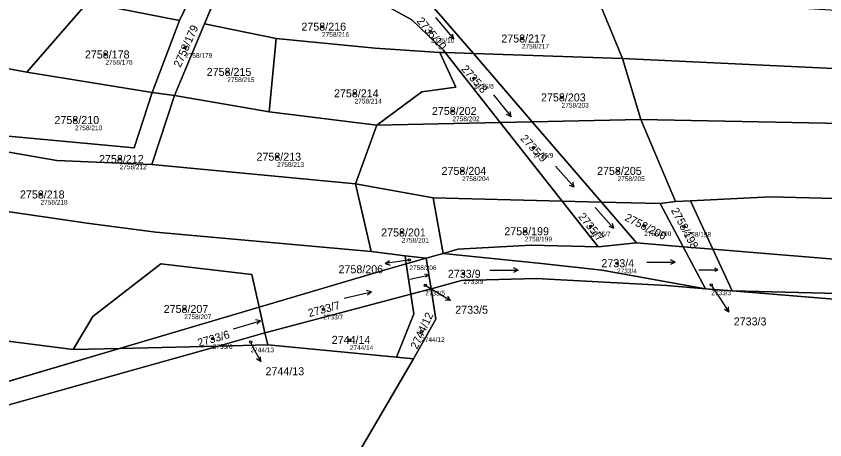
# Model space of a CAD drawing. Extents: x -739214 to -733252, y -1147612 to -1142842.
# Drawn here: x -737857.5 to -737685.7, y -1144474 to -1144384.1 of the extents above; entities that cross this region are included whole.
import ezdxf

# ---------------------------------------------------------------- set-up
doc = ezdxf.new("R2010")
doc.units = 0
for name, color, linetype in [('Definiční body', 7, 'Continuous'), ('Hranice parcel', 7, 'Continuous'), ('Parcelní čísla', 7, 'Continuous'), ('Polygon parcely', 7, 'Continuous'), ('Pop  PČ popisy', 7, 'Continuous'), ('Značky kultur', 7, 'Continuous')]:
    doc.layers.add(name, color=color, linetype=linetype)

msp = doc.modelspace()

# ---------------------------------------------------------------- linework, layer by layer
at = {"layer": 'Definiční body'}
for centre in [(-737792.56, -1144386.29), (-737769.43, -1144387.53), (-737750.1, -1144388.81), (-737821.63, -1144390.75), (-737838.55, -1144392.2), (-737812.68, -1144395.9), (-737760.29, -1144397.29), (-737785.64, -1144400.45), (-737741.66, -1144401.32), (-737764.84, -1144404.2), (-737845.01, -1144406.12), (-737747.64, -1144411.98), (-737835.55, -1144414.41), (-737802.1, -1144413.91), (-737762.79, -1144416.92), (-737729.76, -1144416.92), (-737852.35, -1144421.92), (-737735.48, -1144428.69), (-737724.13, -1144428.58), (-737715.67, -1144428.74), (-737775.62, -1144429.99), (-737749.46, -1144429.73), (-737773.99, -1144435.82), (-737729.9, -1144436.51), (-737762.51, -1144438.76), (-737770.64, -1144441.21), (-737709.88, -1144441.15), (-737821.82, -1144446.23), (-737792.3, -1144446.29), (-737771.49, -1144451.07), (-737815.77, -1144452.55), (-737786.65, -1144452.79), (-737807.74, -1144453.26)]:
    msp.add_circle(centre, 0.25, dxfattribs=at)
at = {"layer": 'Hranice parcel'}
for p, q in [((-737819.16, -1144377.29), (-737822.86, -1144384.96)), ((-737817.51, -1144385.68), (-737814.34, -1144378.15)), ((-737855.23, -1144395.98), (-737842.4, -1144381.17)), ((-737822.86, -1144384.96), (-737842.4, -1144381.17)), ((-737760.41, -1144392.01), (-737769.21, -1144381.81)), ((-737733.64, -1144381.24), (-737728.72, -1144393.06)), ((-737828.63, -1144400.28), (-737822.86, -1144384.96)), ((-737823.9, -1144400.88), (-737817.51, -1144385.68)), ((-737802.29, -1144388.83), (-737817.51, -1144385.68)), ((-737802.29, -1144388.83), (-737803.75, -1144404.41)), ((-737766.39, -1144391.81), (-737767.52, -1144391.77)), ((-737760.41, -1144392.01), (-737766.39, -1144391.81)), ((-737766.39, -1144391.81), (-737754.7, -1144406.64)), ((-737747.91, -1144406.5), (-737760.41, -1144392.01)), ((-737728.72, -1144393.06), (-737760.41, -1144392.01)), ((-737728.72, -1144393.06), (-737724.82, -1144406.02)), ((-737860.24, -1144395.01), (-737855.23, -1144395.98)), ((-737855.23, -1144395.98), (-737828.63, -1144400.28)), ((-737828.71, -1144415.54), (-737823.9, -1144400.88)), ((-737828.63, -1144400.28), (-737823.9, -1144400.88)), ((-737780.88, -1144407.18), (-737803.75, -1144404.41)), ((-737747.91, -1144406.5), (-737724.82, -1144406.02)), ((-737724.82, -1144406.02), (-737717.47, -1144423.41)), ((-737780.88, -1144407.18), (-737785.47, -1144419.68)), ((-737780.88, -1144407.18), (-737754.7, -1144406.64)), ((-737754.7, -1144406.64), (-737747.91, -1144406.5)), ((-737754.7, -1144406.64), (-737741.55, -1144423.32)), ((-737733.22, -1144423.53), (-737747.91, -1144406.5)), ((-737828.71, -1144415.54), (-737785.47, -1144419.68)), ((-737768.93, -1144422.63), (-737785.47, -1144419.68)), ((-737785.47, -1144419.68), (-737782.1, -1144434.06)), ((-737741.55, -1144423.32), (-737768.93, -1144422.63)), ((-737768.93, -1144422.63), (-737766.81, -1144434.44)), ((-737733.22, -1144423.53), (-737741.55, -1144423.32)), ((-737741.55, -1144423.32), (-737733.87, -1144433.07)), ((-737717.47, -1144423.41), (-737720.76, -1144423.85)), ((-737717.47, -1144423.41), (-737714.28, -1144423.29)), ((-737714.28, -1144423.29), (-737709.52, -1144433.54)), ((-737720.76, -1144423.85), (-737733.22, -1144423.53)), ((-737725.73, -1144432.21), (-737733.22, -1144423.53)), ((-737720.76, -1144423.85), (-737715.85, -1144433.02)), ((-737725.73, -1144432.21), (-737733.87, -1144433.07)), ((-737715.85, -1144433.02), (-737725.73, -1144432.21)), ((-737709.52, -1144433.54), (-737715.85, -1144433.02)), ((-737715.85, -1144433.02), (-737711.09, -1144441.92)), ((-737709.52, -1144433.54), (-737705.41, -1144442.38)), ((-737782.1, -1144434.06), (-737774.89, -1144434.96)), ((-737774.89, -1144434.96), (-737770.45, -1144435.47)), ((-737774.89, -1144434.96), (-737774.65, -1144436.65)), ((-737766.81, -1144434.44), (-737770.45, -1144435.47)), ((-737770.45, -1144435.47), (-737774.65, -1144436.65)), ((-737774.65, -1144436.65), (-737773.72, -1144443.09)), ((-737769.4, -1144441.94), (-737770.45, -1144435.47)), ((-737773.72, -1144443.09), (-737769.4, -1144441.94)), ((-737711.09, -1144441.92), (-737705.41, -1144442.38)), ((-737805.91, -1144445.83), (-737835.54, -1144454.6)), ((-737804.67, -1144451.31), (-737805.91, -1144445.83)), ((-737814.62, -1144454.1), (-737804.67, -1144451.31)), ((-737804.09, -1144453.85), (-737804.67, -1144451.31)), ((-737835.54, -1144454.6), (-737814.62, -1144454.1)), ((-737814.62, -1144454.1), (-737804.09, -1144453.85)), ((-737804.09, -1144453.85), (-737776.7, -1144456.47)), ((-737835.54, -1144454.6), (-737868.17, -1144464.26)), ((-737845.4, -1144454.84), (-737835.54, -1144454.6)), ((-737773.14, -1144456.81), (-737785.6, -1144478.09)), ((-737776.7, -1144456.47), (-737773.14, -1144456.81))]:
    msp.add_line(p, q, dxfattribs=at)
for points in [[(-737779.31, -1144381.64), (-737773.51, -1144384.84), (-737766.78, -1144391.31), (-737766.39, -1144391.81)], [(-737767.52, -1144391.77), (-737781.29, -1144390.88), (-737802.29, -1144388.83)], [(-737767.52, -1144391.77), (-737764.14, -1144399.15), (-737771.37, -1144400.16), (-737780.88, -1144407.18)], [(-737728.72, -1144393.06), (-737671.96, -1144395.77), (-737644.37, -1144397.73), (-737563.33, -1144405.98), (-737533.61, -1144409.53), (-737522.36, -1144411.87)], [(-737861.54, -1144409.35), (-737832.48, -1144412.05), (-737828.63, -1144400.28)], [(-737803.75, -1144404.41), (-737816.86, -1144402.11), (-737823.9, -1144400.88)], [(-737922.34, -1144401.98), (-737848.89, -1144414.72), (-737828.71, -1144415.54)], [(-737724.82, -1144406.02), (-737667.68, -1144407.14), (-737645.7, -1144408.73), (-737578.7, -1144416.54), (-737542.83, -1144418.76), (-737511.58, -1144424.84)], [(-737782.1, -1144434.06), (-737827.86, -1144429.94), (-737841.91, -1144428.1), (-737862.38, -1144425.14), (-737892.14, -1144419.93), (-737902.55, -1144419.58)], [(-737714.28, -1144423.29), (-737697.3, -1144422.44), (-737656.3, -1144423.47), (-737595.77, -1144428.44), (-737567.24, -1144431.75), (-737536.74, -1144436.49), (-737506.96, -1144442.22)], [(-737733.87, -1144433.07), (-737748.16, -1144432.7), (-737763.67, -1144433.56), (-737766.81, -1144434.44)], [(-737508.98, -1144449), (-737525.71, -1144447.34), (-737574.46, -1144443.16), (-737649.45, -1144438.49), (-737709.52, -1144433.54)], [(-737766.81, -1144434.44), (-737745.91, -1144436.61), (-737733.14, -1144437.96), (-737711.09, -1144441.92)], [(-737805.91, -1144445.83), (-737807.47, -1144438.93), (-737826.82, -1144436.68), (-737841.25, -1144447.8), (-737845.4, -1144454.84)], [(-737774.65, -1144436.65), (-737778.65, -1144437.77), (-737805.91, -1144445.83)], [(-737769.4, -1144441.94), (-737762.92, -1144440.22), (-737747.06, -1144439.73), (-737719.38, -1144441.24), (-737711.09, -1144441.92)], [(-737773.14, -1144456.81), (-737768.36, -1144448.37), (-737769.4, -1144441.94)], [(-737804.67, -1144451.31), (-737804.16, -1144451.17), (-737773.72, -1144443.09)], [(-737773.72, -1144443.09), (-737773.05, -1144447.28), (-737776.7, -1144456.47)], [(-737705.41, -1144442.38), (-737657.5, -1144443.59), (-737619.63, -1144446.07), (-737595.13, -1144448.36), (-737569.83, -1144452.11)], [(-737705.41, -1144442.38), (-737650.15, -1144446.91), (-737583.62, -1144450.77), (-737569.83, -1144452.11)], [(-737902.69, -1144445.41), (-737872.51, -1144451.39), (-737845.4, -1144454.84)], [(-737926.39, -1144533.41), (-737927.01, -1144530.86), (-737925.24, -1144519.57), (-737921.26, -1144511.11), (-737911.32, -1144499.46), (-737900.13, -1144489.08), (-737888.65, -1144480.5), (-737876.41, -1144472.62), (-737867.2, -1144468.83), (-737814.62, -1144454.1)]]:
    msp.add_lwpolyline(points, dxfattribs=at)
at = {"layer": 'Polygon parcely'}
for points in [[(-737966.75, -1144376.24), (-737922.57, -1144381.31), (-737912.63, -1144384.83), (-737860.24, -1144395.01), (-737855.23, -1144395.98), (-737842.4, -1144381.17), (-737839.61, -1144374.13), (-737873.57, -1144366.58), (-737914.15, -1144364.19), (-737952.35, -1144361.12)], [(-737785.6, -1144478.09), (-737773.14, -1144456.81), (-737776.7, -1144456.47), (-737804.09, -1144453.85), (-737814.62, -1144454.1), (-737867.2, -1144468.83), (-737876.41, -1144472.62), (-737888.65, -1144480.5)]]:
    msp.add_lwpolyline(points, dxfattribs=at)
for points in [[(-737819.16, -1144377.29), (-737839.61, -1144374.13), (-737842.4, -1144381.17), (-737822.86, -1144384.96)], [(-737814.34, -1144378.15), (-737819.16, -1144377.29), (-737822.86, -1144384.96), (-737828.63, -1144400.28), (-737823.9, -1144400.88), (-737817.51, -1144385.68)], [(-737766.39, -1144391.81), (-737766.78, -1144391.31), (-737773.51, -1144384.84), (-737779.31, -1144381.64), (-737814.34, -1144378.15), (-737817.51, -1144385.68), (-737802.29, -1144388.83), (-737781.29, -1144390.88), (-737767.52, -1144391.77)], [(-737822.86, -1144384.96), (-737842.4, -1144381.17), (-737855.23, -1144395.98), (-737828.63, -1144400.28)], [(-737766.78, -1144391.31), (-737766.39, -1144391.81), (-737760.41, -1144392.01), (-737769.21, -1144381.81), (-737779.31, -1144381.64), (-737773.51, -1144384.84)], [(-737769.21, -1144381.81), (-737760.41, -1144392.01), (-737728.72, -1144393.06), (-737733.64, -1144381.24), (-737756.43, -1144382.02)], [(-737644.37, -1144397.73), (-737563.33, -1144405.98), (-737533.61, -1144409.53), (-737522.36, -1144411.87), (-737539.01, -1144399.35), (-737578.1, -1144394.75), (-737595.96, -1144391.65), (-737628.78, -1144388.05), (-737682.31, -1144382.93), (-737717.97, -1144380.71), (-737733.64, -1144381.24), (-737728.72, -1144393.06), (-737671.96, -1144395.77)], [(-737817.51, -1144385.68), (-737823.9, -1144400.88), (-737816.86, -1144402.11), (-737803.75, -1144404.41), (-737802.29, -1144388.83)], [(-737781.29, -1144390.88), (-737802.29, -1144388.83), (-737803.75, -1144404.41), (-737780.88, -1144407.18), (-737771.37, -1144400.16), (-737764.14, -1144399.15), (-737767.52, -1144391.77)], [(-737780.88, -1144407.18), (-737754.7, -1144406.64), (-737766.39, -1144391.81), (-737767.52, -1144391.77), (-737764.14, -1144399.15), (-737771.37, -1144400.16)], [(-737747.91, -1144406.5), (-737760.41, -1144392.01), (-737766.39, -1144391.81), (-737754.7, -1144406.64)], [(-737728.72, -1144393.06), (-737760.41, -1144392.01), (-737747.91, -1144406.5), (-737724.82, -1144406.02)], [(-737724.82, -1144406.02), (-737667.68, -1144407.14), (-737645.7, -1144408.73), (-737578.7, -1144416.54), (-737542.83, -1144418.76), (-737511.58, -1144424.84), (-737522.36, -1144411.87), (-737533.61, -1144409.53), (-737563.33, -1144405.98), (-737644.37, -1144397.73), (-737671.96, -1144395.77), (-737728.72, -1144393.06)], [(-737832.48, -1144412.05), (-737828.63, -1144400.28), (-737855.23, -1144395.98), (-737860.24, -1144395.01), (-737861.54, -1144409.35)], [(-737828.71, -1144415.54), (-737823.9, -1144400.88), (-737828.63, -1144400.28), (-737832.48, -1144412.05), (-737861.54, -1144409.35), (-737912.72, -1144401.21), (-737922.34, -1144401.98), (-737848.89, -1144414.72)], [(-737803.75, -1144404.41), (-737816.86, -1144402.11), (-737823.9, -1144400.88), (-737828.71, -1144415.54), (-737785.47, -1144419.68), (-737780.88, -1144407.18)], [(-737902.55, -1144419.58), (-737892.14, -1144419.93), (-737862.38, -1144425.14), (-737841.91, -1144428.1), (-737827.86, -1144429.94), (-737782.1, -1144434.06), (-737785.47, -1144419.68), (-737828.71, -1144415.54), (-737848.89, -1144414.72), (-737922.34, -1144401.98), (-737925.92, -1144419.24)], [(-737747.91, -1144406.5), (-737733.22, -1144423.53), (-737720.76, -1144423.85), (-737717.47, -1144423.41), (-737724.82, -1144406.02)], [(-737567.24, -1144431.75), (-737536.74, -1144436.49), (-737506.96, -1144442.22), (-737505.92, -1144434.94), (-737511.58, -1144424.84), (-737542.83, -1144418.76), (-737578.7, -1144416.54), (-737645.7, -1144408.73), (-737667.68, -1144407.14), (-737724.82, -1144406.02), (-737717.47, -1144423.41), (-737714.28, -1144423.29), (-737697.3, -1144422.44), (-737656.3, -1144423.47), (-737595.77, -1144428.44)], [(-737785.47, -1144419.68), (-737768.93, -1144422.63), (-737741.55, -1144423.32), (-737754.7, -1144406.64), (-737780.88, -1144407.18)], [(-737741.55, -1144423.32), (-737733.22, -1144423.53), (-737747.91, -1144406.5), (-737754.7, -1144406.64)], [(-737872.51, -1144451.39), (-737845.4, -1144454.84), (-737841.25, -1144447.8), (-737826.82, -1144436.68), (-737807.47, -1144438.93), (-737805.91, -1144445.83), (-737778.65, -1144437.77), (-737774.65, -1144436.65), (-737774.89, -1144434.96), (-737782.1, -1144434.06), (-737827.86, -1144429.94), (-737841.91, -1144428.1), (-737862.38, -1144425.14), (-737892.14, -1144419.93), (-737902.55, -1144419.58), (-737902.69, -1144445.41)], [(-737770.45, -1144435.47), (-737766.81, -1144434.44), (-737768.93, -1144422.63), (-737785.47, -1144419.68), (-737782.1, -1144434.06), (-737774.89, -1144434.96)], [(-737766.81, -1144434.44), (-737763.67, -1144433.56), (-737748.16, -1144432.7), (-737733.87, -1144433.07), (-737741.55, -1144423.32), (-737768.93, -1144422.63)], [(-737733.87, -1144433.07), (-737725.73, -1144432.21), (-737733.22, -1144423.53), (-737741.55, -1144423.32)], [(-737715.85, -1144433.02), (-737709.52, -1144433.54), (-737714.28, -1144423.29), (-737717.47, -1144423.41), (-737720.76, -1144423.85)], [(-737709.52, -1144433.54), (-737649.45, -1144438.49), (-737574.46, -1144443.16), (-737525.71, -1144447.34), (-737508.98, -1144449), (-737506.96, -1144442.22), (-737536.74, -1144436.49), (-737567.24, -1144431.75), (-737595.77, -1144428.44), (-737656.3, -1144423.47), (-737697.3, -1144422.44), (-737714.28, -1144423.29)], [(-737720.76, -1144423.85), (-737733.22, -1144423.53), (-737725.73, -1144432.21), (-737715.85, -1144433.02)], [(-737766.81, -1144434.44), (-737745.91, -1144436.61), (-737733.14, -1144437.96), (-737711.09, -1144441.92), (-737715.85, -1144433.02), (-737725.73, -1144432.21), (-737733.87, -1144433.07), (-737748.16, -1144432.7), (-737763.67, -1144433.56)], [(-737711.09, -1144441.92), (-737705.41, -1144442.38), (-737709.52, -1144433.54), (-737715.85, -1144433.02)], [(-737657.5, -1144443.59), (-737619.63, -1144446.07), (-737595.13, -1144448.36), (-737569.83, -1144452.11), (-737527.07, -1144456.26), (-737511.53, -1144457.57), (-737508.98, -1144449), (-737525.71, -1144447.34), (-737574.46, -1144443.16), (-737649.45, -1144438.49), (-737709.52, -1144433.54), (-737705.41, -1144442.38)], [(-737774.65, -1144436.65), (-737770.45, -1144435.47), (-737774.89, -1144434.96)], [(-737711.09, -1144441.92), (-737733.14, -1144437.96), (-737745.91, -1144436.61), (-737766.81, -1144434.44), (-737770.45, -1144435.47), (-737769.4, -1144441.94), (-737762.92, -1144440.22), (-737747.06, -1144439.73), (-737719.38, -1144441.24)], [(-737835.54, -1144454.6), (-737805.91, -1144445.83), (-737807.47, -1144438.93), (-737826.82, -1144436.68), (-737841.25, -1144447.8), (-737845.4, -1144454.84)], [(-737778.65, -1144437.77), (-737805.91, -1144445.83), (-737804.67, -1144451.31), (-737804.16, -1144451.17), (-737773.72, -1144443.09), (-737774.65, -1144436.65)], [(-737774.65, -1144436.65), (-737773.72, -1144443.09), (-737769.4, -1144441.94), (-737770.45, -1144435.47)], [(-737676.5, -1144489.26), (-737627.87, -1144492.95), (-737616.17, -1144494.42), (-737600.37, -1144496.74), (-737576.07, -1144501.23), (-737531.09, -1144511.5), (-737529.44, -1144511.78), (-737526.15, -1144491.59), (-737527.8, -1144458.01), (-737551.39, -1144455.57), (-737569.83, -1144452.11), (-737583.62, -1144450.77), (-737650.15, -1144446.91), (-737705.41, -1144442.38), (-737711.09, -1144441.92), (-737719.38, -1144441.24), (-737747.06, -1144439.73), (-737762.92, -1144440.22), (-737769.4, -1144441.94), (-737768.36, -1144448.37), (-737773.14, -1144456.81), (-737785.6, -1144478.09), (-737733.45, -1144484.87), (-737701.09, -1144487.96)], [(-737773.14, -1144456.81), (-737768.36, -1144448.37), (-737769.4, -1144441.94), (-737773.72, -1144443.09), (-737773.05, -1144447.28), (-737776.7, -1144456.47)], [(-737776.7, -1144456.47), (-737773.05, -1144447.28), (-737773.72, -1144443.09), (-737804.16, -1144451.17), (-737804.67, -1144451.31), (-737804.09, -1144453.85)], [(-737583.62, -1144450.77), (-737569.83, -1144452.11), (-737595.13, -1144448.36), (-737619.63, -1144446.07), (-737657.5, -1144443.59), (-737705.41, -1144442.38), (-737650.15, -1144446.91)], [(-737955.11, -1144459.11), (-737934.96, -1144460.74), (-737868.17, -1144464.26), (-737835.54, -1144454.6), (-737845.4, -1144454.84), (-737872.51, -1144451.39), (-737902.69, -1144445.41), (-737955.28, -1144448.06)], [(-737805.91, -1144445.83), (-737835.54, -1144454.6), (-737814.62, -1144454.1), (-737804.67, -1144451.31)], [(-737804.09, -1144453.85), (-737804.67, -1144451.31), (-737814.62, -1144454.1)], [(-737931.41, -1144530.71), (-737930.97, -1144533.06), (-737926.39, -1144533.41), (-737927.01, -1144530.86), (-737925.24, -1144519.57), (-737921.26, -1144511.11), (-737911.32, -1144499.46), (-737900.13, -1144489.08), (-737888.65, -1144480.5), (-737876.41, -1144472.62), (-737867.2, -1144468.83), (-737814.62, -1144454.1), (-737835.54, -1144454.6), (-737868.17, -1144464.26), (-737877.57, -1144468.52), (-737891.83, -1144477.32), (-737904.38, -1144486.62), (-737914.24, -1144496.47), (-737925.02, -1144509.31), (-737929.6, -1144518.25), (-737930.48, -1144525.51)]]:
    msp.add_lwpolyline(points, close=True, dxfattribs=at)
at = {"layer": 'Pop  PČ popisy'}
for p, q in [((-737779.16, -1144436.55), (-737778.24, -1144435.91)), ((-737776.19, -1144436.13), (-737779.16, -1144436.55)), ((-737779.16, -1144436.55), (-737778.1, -1144436.9)), ((-737773.99, -1144435.82), (-737776.19, -1144436.13)), ((-737770.64, -1144441.21), (-737767.83, -1144442.88)), ((-737709.88, -1144441.15), (-737707.75, -1144444.39)), ((-737767.83, -1144442.88), (-737765.26, -1144444.43)), ((-737765.26, -1144444.43), (-737765.86, -1144443.48)), ((-737765.26, -1144444.43), (-737766.37, -1144444.34)), ((-737707.75, -1144444.39), (-737706.12, -1144446.91)), ((-737706.12, -1144446.91), (-737707.08, -1144446.34)), ((-737706.12, -1144446.91), (-737706.24, -1144445.79)), ((-737807.74, -1144453.26), (-737806.94, -1144454.81)), ((-737806.94, -1144454.81), (-737805.58, -1144457.48)), ((-737805.58, -1144457.48), (-737806.48, -1144456.82)), ((-737805.58, -1144457.48), (-737805.59, -1144456.36))]:
    msp.add_line(p, q, dxfattribs=at)
at = {"layer": 'Značky kultur'}
for p, q in [((-737768.42, -1144384.36), (-737764.57, -1144388.96)), ((-737764.57, -1144388.96), (-737765.58, -1144388.53)), ((-737764.57, -1144388.96), (-737764.81, -1144387.89)), ((-737756.14, -1144400.75), (-737752.37, -1144405.41)), ((-737752.37, -1144405.41), (-737752.59, -1144404.33)), ((-737752.37, -1144405.41), (-737753.37, -1144404.97)), ((-737742.98, -1144415.92), (-737738.97, -1144420.38)), ((-737738.97, -1144420.38), (-737739.99, -1144419.99)), ((-737738.97, -1144420.38), (-737739.25, -1144419.32)), ((-737734.55, -1144424.68), (-737730.54, -1144429.14)), ((-737730.54, -1144429.14), (-737730.82, -1144428.08)), ((-737730.54, -1144429.14), (-737731.56, -1144428.75)), ((-737723.57, -1144436.3), (-737717.57, -1144436.3)), ((-737717.57, -1144436.3), (-737718.55, -1144435.8)), ((-737717.57, -1144436.3), (-737718.55, -1144436.8)), ((-737769.97, -1144439.04), (-737770.68, -1144438.85)), ((-737756.9, -1144438.02), (-737750.9, -1144438.02)), ((-737750.9, -1144438.02), (-737751.88, -1144437.52)), ((-737750.9, -1144438.02), (-737751.88, -1144438.52)), ((-737712.5, -1144437.92), (-737708.48, -1144437.92)), ((-737708.48, -1144437.92), (-737709.13, -1144437.58)), ((-737708.48, -1144437.92), (-737709.13, -1144438.25)), ((-737773.9, -1144439.88), (-737769.97, -1144439.04)), ((-737769.97, -1144439.04), (-737770.54, -1144439.51)), ((-737782.03, -1144442.57), (-737783.09, -1144442.3)), ((-737787.87, -1144443.92), (-737782.03, -1144442.57)), ((-737782.03, -1144442.57), (-737782.87, -1144443.28)), ((-737811.34, -1144450.47), (-737805.6, -1144448.72)), ((-737805.6, -1144448.72), (-737806.68, -1144448.52)), ((-737805.6, -1144448.72), (-737806.39, -1144449.48))]:
    msp.add_line(p, q, dxfattribs=at)

# ---------------------------------------------------------------- texts
at = {"layer": 'Definiční body'}
for s, p in [('2758/216', (-737792.56, -1144388.45)), ('2735/10', (-737769.43, -1144389.69)), ('2758/217', (-737750.1, -1144390.97)), ('2758/179', (-737821.63, -1144392.91)), ('2758/178', (-737838.55, -1144394.36)), ('2758/215', (-737812.68, -1144398.06)), ('2735/8', (-737760.29, -1144399.45)), ('2758/214', (-737785.64, -1144402.61)), ('2758/203', (-737741.66, -1144403.48)), ('2758/202', (-737764.84, -1144406.36)), ('2758/210', (-737845.01, -1144408.28)), ('2735/9', (-737747.64, -1144414.14)), ('2758/212', (-737835.55, -1144416.57)), ('2758/213', (-737802.1, -1144416.07)), ('2758/204', (-737762.79, -1144419.08)), ('2758/205', (-737729.76, -1144419.08)), ('2758/218', (-737852.35, -1144424.08)), ('2735/7', (-737735.48, -1144430.85)), ('2758/200', (-737724.13, -1144430.74)), ('2758/198', (-737715.67, -1144430.9)), ('2758/201', (-737775.62, -1144432.15)), ('2758/199', (-737749.46, -1144431.89)), ('2758/206', (-737773.99, -1144437.98)), ('2733/4', (-737729.9, -1144438.67)), ('2733/9', (-737762.51, -1144440.92)), ('2733/5', (-737770.64, -1144443.37)), ('2733/3', (-737709.88, -1144443.31)), ('2758/207', (-737821.82, -1144448.39)), ('2733/7', (-737792.3, -1144448.45)), ('2744/12', (-737771.49, -1144453.23)), ('2733/6', (-737815.77, -1144454.71)), ('2744/14', (-737786.65, -1144454.95)), ('2744/13', (-737807.74, -1144455.42))]:
    msp.add_text(s, height=1, dxfattribs=at).set_placement(p)
at = {"layer": 'Parcelní čísla'}
for s, p in [('2758/216', (-737796.93, -1144387.14)), ('2758/217', (-737754.47, -1144389.66)), ('2758/178', (-737842.92, -1144393.05)), ('2758/215', (-737817.05, -1144396.75)), ('2758/214', (-737790.01, -1144401.3)), ('2758/203', (-737746.03, -1144402.17)), ('2758/202', (-737769.21, -1144405.05)), ('2758/210', (-737849.38, -1144406.97)), ('2758/213', (-737806.47, -1144414.76)), ('2758/212', (-737839.92, -1144415.26)), ('2758/204', (-737767.16, -1144417.77)), ('2758/205', (-737734.13, -1144417.77)), ('2758/218', (-737856.72, -1144422.77)), ('2758/201', (-737779.99, -1144430.84)), ('2758/199', (-737753.83, -1144430.58)), ('2758/206', (-737789.05, -1144438.65)), ('2733/4', (-737733.2, -1144437.36)), ('2733/9', (-737765.82, -1144439.61)), ('2758/207', (-737826.19, -1144447.08)), ('2733/5', (-737764.25, -1144447.24)), ('2733/3', (-737705.1, -1144449.73)), ('2744/14', (-737790.49, -1144453.64)), ('2744/13', (-737804.56, -1144460.31))]:
    msp.add_text(s, height=1.7, dxfattribs=at).set_placement(p)
for s, rotation, p in [('2735/10', 310, (-737772.55, -1144385.14)), ('2758/179', 66, (-737822.63, -1144395.09)), ('2735/8', 311, (-737763.1, -1144395.35)), ('2735/9', 313, (-737750.52, -1144410.14)), ('2758/198', 298, (-737718.47, -1144425.28)), ('2735/7', 309, (-737738.22, -1144426.66)), ('2758/200', 333, (-737728.41, -1144427.35)), ('2733/7', 15, (-737795.27, -1144447.97)), ('2744/12', 65, (-737772.34, -1144454.91)), ('2733/6', 16, (-737818.71, -1144454.28))]:
    msp.add_text(s, height=1.7, rotation=rotation, dxfattribs=at).set_placement(p)

doc.saveas('drawing.dxf')
